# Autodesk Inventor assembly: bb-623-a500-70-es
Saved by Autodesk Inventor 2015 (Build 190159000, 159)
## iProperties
Created: 2022-04
Part Number: bb-623-a500-70-es
Checked By: TraceParts S.A.
Catalog Web Link: www.traceparts.com
Document SubType Name: Assembly
Designer: TraceParts
Company: TraceParts S.A.
Author: TraceParts
REFERENCE: BB-623-A500-70-ES
rs_stock_number: 7026753
SUPPLIER_NAME: RS Components
Buy_Now: https://uk.rs-online.com/web/p/products/7026753?cm_mmc=en-ds-_-mcad-_-traceparts-_-7026753'
SUPPLIER: Igus
DESIGN: Rillenkugellager Kugellager 1-reihig, Igus BB-623-A500-70-ES, Innen-Ø 3mm, Außen-Ø 10mm
TraceParts.PartNumber: 10-25012011-082319
TraceParts.PartTitle: Rillenkugellager Kugellager 1-reihig, Igus BB-623-A500-70-ES, Innen-Ø 3mm, Außen-Ø 10mm
TraceParts.InstanceId: 10-25012011-0823194CKMS95UDXO2E0BG6SXDZ1VDK
TraceParts.PartVersion: 1.1.7
TraceParts.PartLanguage: de
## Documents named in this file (15)
- C:\TPO v2\SharedFS\Outgoing\bb-623-a500-70-es.iam
- C:\TPO v2\SharedFS\Outgoing\bb-623-a500-70-es_01.ipt
- C:\TPO v2\SharedFS\Outgoing\bb-623-a500-70-es_02.ipt
- C:\TPO v2\SharedFS\Outgoing\bb-623-a500-70-es_03.ipt
- C:\TPO v2\SharedFS\Outgoing\bb-623-a500-70-es_04.ipt
- C:\TPO v2\SharedFS\Outgoing\bb-623-a500-70-es_05.ipt
- C:\TPO v2\SharedFS\Outgoing\bb-623-a500-70-es_06.ipt
- C:\TPO v2\SharedFS\Outgoing\bb-623-a500-70-es_07.ipt
- C:\TPO v2\SharedFS\Outgoing\bb-623-a500-70-es_08.ipt
- C:\TPO v2\SharedFS\Outgoing\bb-623-a500-70-es_09.ipt
- C:\TPO v2\SharedFS\Outgoing\bb-623-a500-70-es_10.ipt
- C:\TPO v2\SharedFS\Outgoing\bb-623-a500-70-es_11.ipt
- C:\TPO v2\SharedFS\Outgoing\bb-623-a500-70-es_12.ipt
- C:\TPO v2\SharedFS\Outgoing\bb-623-a500-70-es_13.ipt
- C:\TPO v2\SharedFS\Outgoing\bb-623-a500-70-es_14.ipt
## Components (14 placed, 14 different names)
1. bb-623-a500-70-es_01:1
2. bb-623-a500-70-es_02:1
3. bb-623-a500-70-es_03:1
4. bb-623-a500-70-es_04:1
5. bb-623-a500-70-es_05:1
6. bb-623-a500-70-es_06:1
7. bb-623-a500-70-es_07:1
8. bb-623-a500-70-es_08:1
9. bb-623-a500-70-es_09:1
10. bb-623-a500-70-es_10:1
11. bb-623-a500-70-es_11:1
12. bb-623-a500-70-es_12:1
13. bb-623-a500-70-es_13:1
14. bb-623-a500-70-es_14:1
